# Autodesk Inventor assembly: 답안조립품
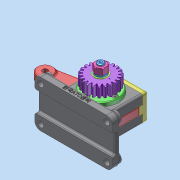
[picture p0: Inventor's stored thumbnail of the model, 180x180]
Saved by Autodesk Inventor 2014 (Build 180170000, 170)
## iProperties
Created: 2026-03
Part Number: 답안조립품
Document SubType Name: Assembly
Designer: dg
Mass: 1676.99 g
Surface Area: 1011.01 cm^2
Volume: 333.535 cm^3
Density: 5.02792 g/cm^3
Author: dg
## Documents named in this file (15)
- C:\Users\dg\Desktop\660303V1005\답안조립품.iam
- C:\Users\dg\Desktop\660303V1005\가져온 구성요소\본체\본체.ipt
- C:\Users\dg\Desktop\660303V1005\가져온 구성요소\로드\로드.ipt
- C:\Users\dg\Desktop\660303V1005\가져온 구성요소\편심축\편심축.ipt
- C:\Users\dg\Desktop\660303V1005\가져온 구성요소\플랜지 오일레스 부시\플랜지 오일레스 부시.ipt
- C:\Users\dg\Desktop\660303V1005\가져온 구성요소\앞커버\앞커버.ipt
- C:\Users\dg\Desktop\660303V1005\가져온 구성요소\윗커버\윗커버.ipt
- C:\Users\dg\Desktop\660303V1005\가져온 구성요소\실링\실링.ipt
- C:\Users\dg\Desktop\660303V1005\가져온 구성요소\스프링와셔 M10\스프링와셔 M10.ipt
- C:\Users\dg\Desktop\660303V1005\가져온 구성요소\평와셔 M10\평와셔 M10.ipt
- C:\Users\dg\Desktop\660303V1005\가져온 구성요소\평행키 4x4x10\평행키 4x4x10.ipt
- C:\Users\dg\Desktop\660303V1005\가져온 구성요소\6각 구멍붙이 볼트 M4x10\6각 구멍붙이 볼트 M4x10.ipt
- C:\Users\dg\Desktop\660303V1005\가져온 구성요소\6각 너트 M10\6각 너트 M10.ipt
- C:\Users\dg\Desktop\660303V1005\가져온 구성요소\그리스 니플 M6x0.75\그리스 니플 M6x0.75.ipt
- C:\Users\dg\Desktop\660303V1005\가져온 구성요소\스퍼기어\스퍼기어.ipt
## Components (12 placed, 4 different names)
1. 플랜지 오일레스 부시:1
2. 플랜지 오일레스 부시:2
3. 6각 너트 M10:1
4. 그리스 니플 M6x0.75:1
5. 6각 구멍붙이 볼트 M4x10:1
6. 6각 구멍붙이 볼트 M4x10:2
7. 6각 구멍붙이 볼트 M4x10:3
8. 6각 구멍붙이 볼트 M4x10:4
9. 6각 구멍붙이 볼트 M4x10:5
10. 6각 구멍붙이 볼트 M4x10:6
11. 6각 구멍붙이 볼트 M4x10:7
12. 6각 구멍붙이 볼트 M4x10:8
